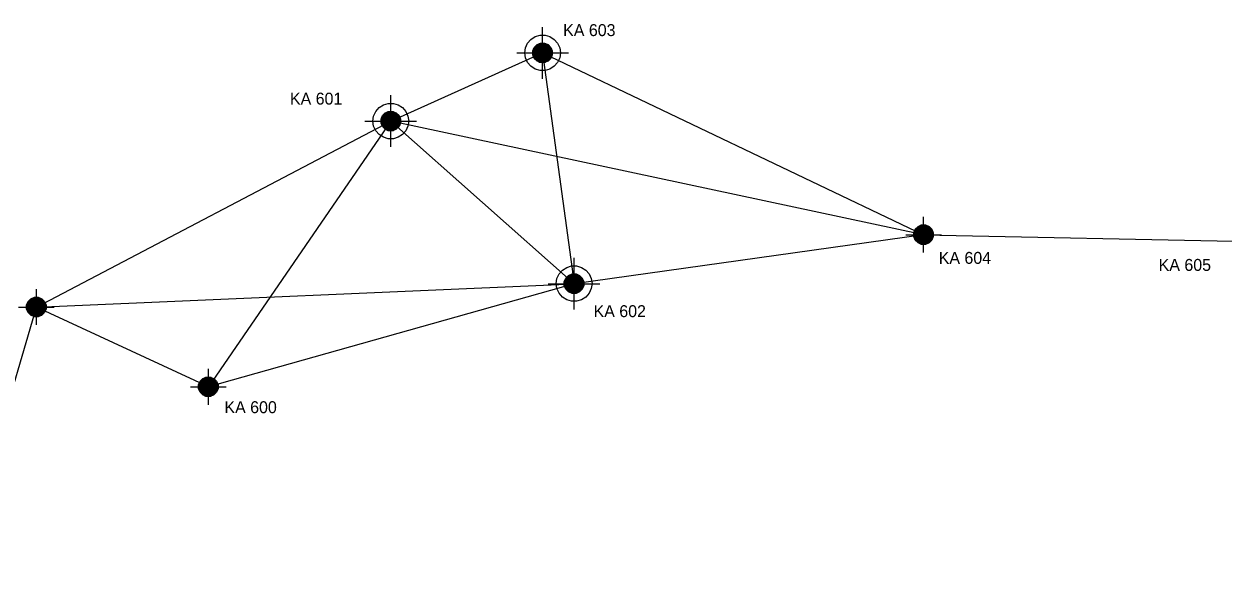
# Model space of a CAD drawing. Extents: x -346533 to -339969, y -1273090 to -1271585.
# Drawn here: x -342735 to -341982, y -1272262 to -1271911 of the extents above; entities that cross this region are included whole.
import ezdxf

# ---------------------------------------------------------------- set-up
doc = ezdxf.new("R2010")
doc.units = 0
for name, color, linetype in [('BP_11', 7, 'Continuous'), ('BP_12', 7, 'Continuous'), ('BP_14', 7, 'Continuous')]:
    doc.layers.add(name, color=color, linetype=linetype)

msp = doc.modelspace()

# ---------------------------------------------------------------- linework, layer by layer
at = {"layer": 'BP_11'}
for points in [[(-342409.41, -1271945.38), (-342409.41, -1271939.03), (-342409.41, -1271932.68), (-342409.41, -1271926.33), (-342409.41, -1271919.98), (-342409.41, -1271913.63), (-342409.41, -1271912.88)], [(-342425.66, -1271929.13), (-342419.31, -1271929.13), (-342412.96, -1271929.13), (-342406.61, -1271929.13), (-342400.26, -1271929.13), (-342393.91, -1271929.13), (-342393.16, -1271929.13)], [(-342409.41, -1271922.98), (-342408.21, -1271922.98), (-342405.96, -1271923.93), (-342404.26, -1271925.63), (-342403.31, -1271927.88), (-342403.31, -1271930.33), (-342404.26, -1271932.58), (-342405.96, -1271934.28), (-342408.21, -1271935.23), (-342410.66, -1271935.23), (-342412.91, -1271934.28), (-342414.61, -1271932.58), (-342415.56, -1271930.33), (-342415.56, -1271927.88), (-342414.61, -1271925.63), (-342412.91, -1271923.93), (-342410.66, -1271922.98), (-342409.46, -1271922.98), (-342407.66, -1271923.33), (-342411.26, -1271923.33), (-342412.06, -1271923.73), (-342406.86, -1271923.73), (-342406.06, -1271924.13), (-342412.41, -1271924.13), (-342412.86, -1271924.13), (-342413.26, -1271924.53), (-342406.91, -1271924.53), (-342405.66, -1271924.53), (-342405.26, -1271924.93), (-342411.61, -1271924.93), (-342413.66, -1271924.93), (-342414.06, -1271925.33), (-342407.71, -1271925.33), (-342404.86, -1271925.33), (-342404.46, -1271925.73), (-342410.81, -1271925.73), (-342414.46, -1271925.73), (-342414.46, -1271926.13), (-342408.11, -1271926.13), (-342404.46, -1271926.13), (-342404.06, -1271926.53), (-342410.41, -1271926.53), (-342414.86, -1271926.53), (-342414.86, -1271926.93), (-342408.51, -1271926.93), (-342404.06, -1271926.93), (-342404.06, -1271927.33), (-342410.41, -1271927.33), (-342414.86, -1271927.33), (-342415.26, -1271927.73), (-342408.91, -1271927.73), (-342403.66, -1271927.73), (-342403.66, -1271928.13), (-342410.01, -1271928.13), (-342415.26, -1271928.13), (-342415.26, -1271928.53), (-342408.91, -1271928.53), (-342403.66, -1271928.53), (-342403.66, -1271928.93), (-342410.01, -1271928.93), (-342415.26, -1271928.93), (-342415.26, -1271929.33), (-342408.91, -1271929.33), (-342403.66, -1271929.33), (-342403.66, -1271929.73), (-342410.01, -1271929.73), (-342415.26, -1271929.73), (-342415.26, -1271930.13), (-342408.91, -1271930.13), (-342403.66, -1271930.13), (-342403.66, -1271930.53), (-342410.01, -1271930.53), (-342415.26, -1271930.53), (-342415.26, -1271930.93), (-342408.91, -1271930.93), (-342403.66, -1271930.93), (-342404.06, -1271931.33), (-342410.41, -1271931.33), (-342414.86, -1271931.33), (-342414.86, -1271931.73), (-342408.51, -1271931.73), (-342404.06, -1271931.73), (-342404.46, -1271932.13), (-342410.81, -1271932.13), (-342414.46, -1271932.13), (-342414.46, -1271932.53), (-342408.11, -1271932.53), (-342404.46, -1271932.53), (-342404.86, -1271932.93), (-342411.21, -1271932.93), (-342414.06, -1271932.93), (-342413.66, -1271933.33), (-342407.31, -1271933.33), (-342405.26, -1271933.33), (-342405.66, -1271933.73), (-342412.01, -1271933.73), (-342413.26, -1271933.73), (-342412.86, -1271934.13), (-342406.51, -1271934.13), (-342406.06, -1271934.13)], [(-342406.06, -1271934.13), (-342406.86, -1271934.53), (-342412.06, -1271934.53), (-342411.26, -1271934.93), (-342407.66, -1271934.93)], [(-342504.81, -1271988.24), (-342504.81, -1271981.89), (-342504.81, -1271975.54), (-342504.81, -1271969.19), (-342504.81, -1271962.84), (-342504.81, -1271956.49), (-342504.81, -1271955.74)], [(-342504.81, -1271965.84), (-342503.61, -1271965.84), (-342501.36, -1271966.79), (-342499.66, -1271968.49), (-342498.71, -1271970.74), (-342498.71, -1271973.19), (-342499.66, -1271975.44), (-342501.36, -1271977.14), (-342503.61, -1271978.09), (-342506.06, -1271978.09), (-342508.31, -1271977.14), (-342510.01, -1271975.44), (-342510.96, -1271973.19), (-342510.96, -1271970.74), (-342510.01, -1271968.49), (-342508.31, -1271966.79), (-342506.06, -1271965.84), (-342504.86, -1271965.84), (-342503.06, -1271966.19), (-342506.66, -1271966.19), (-342507.46, -1271966.59), (-342502.26, -1271966.59), (-342501.46, -1271966.99), (-342507.81, -1271966.99), (-342508.26, -1271966.99), (-342508.66, -1271967.39), (-342502.31, -1271967.39), (-342501.06, -1271967.39), (-342500.66, -1271967.79), (-342507.01, -1271967.79), (-342509.06, -1271967.79), (-342509.46, -1271968.19), (-342503.11, -1271968.19), (-342500.26, -1271968.19), (-342499.86, -1271968.59), (-342506.21, -1271968.59), (-342509.86, -1271968.59), (-342509.86, -1271968.99), (-342503.51, -1271968.99), (-342499.86, -1271968.99), (-342499.46, -1271969.39), (-342505.81, -1271969.39), (-342510.26, -1271969.39), (-342510.26, -1271969.79), (-342503.91, -1271969.79), (-342499.46, -1271969.79), (-342499.46, -1271970.19), (-342505.81, -1271970.19), (-342510.26, -1271970.19), (-342510.66, -1271970.59), (-342504.31, -1271970.59), (-342499.06, -1271970.59), (-342499.06, -1271970.99), (-342505.41, -1271970.99), (-342510.66, -1271970.99), (-342510.66, -1271971.39), (-342504.31, -1271971.39), (-342499.06, -1271971.39), (-342499.06, -1271971.79), (-342505.41, -1271971.79), (-342510.66, -1271971.79), (-342510.66, -1271972.19), (-342504.31, -1271972.19), (-342499.06, -1271972.19), (-342499.06, -1271972.59), (-342505.41, -1271972.59), (-342510.66, -1271972.59), (-342510.66, -1271972.99), (-342504.31, -1271972.99), (-342499.06, -1271972.99), (-342499.06, -1271973.39), (-342505.41, -1271973.39), (-342510.66, -1271973.39), (-342510.66, -1271973.79), (-342504.31, -1271973.79), (-342499.06, -1271973.79), (-342499.46, -1271974.19), (-342505.81, -1271974.19), (-342510.26, -1271974.19), (-342510.26, -1271974.59), (-342503.91, -1271974.59), (-342499.46, -1271974.59), (-342499.86, -1271974.99), (-342506.21, -1271974.99), (-342509.86, -1271974.99), (-342509.86, -1271975.39), (-342503.51, -1271975.39), (-342499.86, -1271975.39), (-342500.26, -1271975.79), (-342506.61, -1271975.79), (-342509.46, -1271975.79), (-342509.06, -1271976.19), (-342502.71, -1271976.19), (-342500.66, -1271976.19), (-342501.06, -1271976.59), (-342507.41, -1271976.59), (-342508.66, -1271976.59), (-342508.26, -1271976.99), (-342501.91, -1271976.99), (-342501.46, -1271976.99)], [(-342521.06, -1271971.99), (-342514.71, -1271971.99), (-342508.36, -1271971.99), (-342502.01, -1271971.99), (-342495.66, -1271971.99), (-342489.31, -1271971.99), (-342488.56, -1271971.99)], [(-342501.46, -1271976.99), (-342502.26, -1271977.39), (-342507.46, -1271977.39), (-342506.66, -1271977.79), (-342503.06, -1271977.79)], [(-342169.95, -1272054.61), (-342169.95, -1272048.26), (-342169.95, -1272041.91), (-342169.95, -1272035.56), (-342169.95, -1272032.11)], [(-342169.95, -1272037.21), (-342168.75, -1272037.21), (-342166.5, -1272038.16), (-342164.8, -1272039.86), (-342163.85, -1272042.11), (-342163.85, -1272044.56), (-342164.8, -1272046.81), (-342166.5, -1272048.51), (-342168.75, -1272049.46), (-342171.2, -1272049.46), (-342173.45, -1272048.51), (-342175.15, -1272046.81), (-342176.1, -1272044.56), (-342176.1, -1272042.11), (-342175.15, -1272039.86), (-342173.45, -1272038.16), (-342171.2, -1272037.21), (-342170, -1272037.21), (-342168.2, -1272037.56), (-342171.8, -1272037.56), (-342172.6, -1272037.96), (-342167.4, -1272037.96), (-342166.6, -1272038.36), (-342172.95, -1272038.36), (-342173.4, -1272038.36), (-342173.8, -1272038.76), (-342167.45, -1272038.76), (-342166.2, -1272038.76), (-342165.8, -1272039.16), (-342172.15, -1272039.16), (-342174.2, -1272039.16), (-342174.6, -1272039.56), (-342168.25, -1272039.56), (-342165.4, -1272039.56), (-342165, -1272039.96), (-342171.35, -1272039.96), (-342175, -1272039.96), (-342175, -1272040.36), (-342168.65, -1272040.36), (-342165, -1272040.36), (-342164.6, -1272040.76), (-342170.95, -1272040.76), (-342175.4, -1272040.76), (-342175.4, -1272041.16), (-342169.05, -1272041.16), (-342164.6, -1272041.16), (-342164.2, -1272041.56), (-342170.55, -1272041.56), (-342175.8, -1272041.56), (-342175.8, -1272041.96), (-342169.45, -1272041.96), (-342164.2, -1272041.96), (-342164.2, -1272042.36), (-342170.55, -1272042.36), (-342175.8, -1272042.36), (-342175.8, -1272042.76), (-342169.45, -1272042.76), (-342164.2, -1272042.76), (-342164.2, -1272043.16), (-342170.55, -1272043.16), (-342175.8, -1272043.16), (-342175.8, -1272043.56), (-342169.45, -1272043.56), (-342164.2, -1272043.56), (-342164.2, -1272043.96), (-342170.55, -1272043.96), (-342175.8, -1272043.96), (-342175.8, -1272044.36), (-342169.45, -1272044.36), (-342164.2, -1272044.36), (-342164.2, -1272044.76), (-342170.55, -1272044.76), (-342175.8, -1272044.76), (-342175.8, -1272045.16), (-342169.45, -1272045.16), (-342164.2, -1272045.16), (-342164.6, -1272045.56), (-342170.95, -1272045.56), (-342175.4, -1272045.56), (-342175.4, -1272045.96), (-342169.05, -1272045.96), (-342164.6, -1272045.96), (-342165, -1272046.36), (-342171.35, -1272046.36), (-342175, -1272046.36), (-342175, -1272046.76), (-342168.65, -1272046.76), (-342165, -1272046.76), (-342165.4, -1272047.16), (-342171.75, -1272047.16), (-342174.6, -1272047.16), (-342174.2, -1272047.56), (-342167.85, -1272047.56), (-342165.8, -1272047.56), (-342166.2, -1272047.96), (-342172.55, -1272047.96), (-342173.8, -1272047.96), (-342173.4, -1272048.36), (-342167.05, -1272048.36), (-342166.6, -1272048.36)], [(-342181.2, -1272043.36), (-342174.85, -1272043.36), (-342168.5, -1272043.36), (-342162.15, -1272043.36), (-342158.7, -1272043.36)], [(-342166.6, -1272048.36), (-342167.4, -1272048.76), (-342172.6, -1272048.76), (-342171.8, -1272049.16), (-342168.2, -1272049.16)], [(-342389.61, -1272090.4), (-342389.61, -1272084.05), (-342389.61, -1272077.7), (-342389.61, -1272071.35), (-342389.61, -1272065), (-342389.61, -1272058.65), (-342389.61, -1272057.9)], [(-342389.61, -1272068), (-342388.41, -1272068), (-342386.16, -1272068.95), (-342384.46, -1272070.65), (-342383.51, -1272072.9), (-342383.51, -1272075.35), (-342384.46, -1272077.6), (-342386.16, -1272079.3), (-342388.41, -1272080.25), (-342390.86, -1272080.25), (-342393.11, -1272079.3), (-342394.81, -1272077.6), (-342395.76, -1272075.35), (-342395.76, -1272072.9), (-342394.81, -1272070.65), (-342393.11, -1272068.95), (-342390.86, -1272068), (-342389.66, -1272068), (-342387.86, -1272068.35), (-342391.46, -1272068.35), (-342392.26, -1272068.75), (-342387.06, -1272068.75), (-342386.26, -1272069.15), (-342392.61, -1272069.15), (-342393.06, -1272069.15), (-342393.46, -1272069.55), (-342387.11, -1272069.55), (-342385.86, -1272069.55), (-342385.46, -1272069.95), (-342391.81, -1272069.95), (-342393.86, -1272069.95), (-342394.26, -1272070.35), (-342387.91, -1272070.35), (-342385.06, -1272070.35), (-342384.66, -1272070.75), (-342391.01, -1272070.75), (-342394.66, -1272070.75), (-342394.66, -1272071.15), (-342388.31, -1272071.15), (-342384.66, -1272071.15), (-342384.26, -1272071.55), (-342390.61, -1272071.55), (-342395.06, -1272071.55), (-342395.06, -1272071.95), (-342388.71, -1272071.95), (-342384.26, -1272071.95), (-342384.26, -1272072.35), (-342390.61, -1272072.35), (-342395.06, -1272072.35), (-342395.46, -1272072.75), (-342389.11, -1272072.75), (-342383.86, -1272072.75), (-342383.86, -1272073.15), (-342390.21, -1272073.15), (-342395.46, -1272073.15), (-342395.46, -1272073.55), (-342389.11, -1272073.55), (-342383.86, -1272073.55), (-342383.86, -1272073.95), (-342390.21, -1272073.95), (-342395.46, -1272073.95), (-342395.46, -1272074.35), (-342389.11, -1272074.35), (-342383.86, -1272074.35), (-342383.86, -1272074.75), (-342390.21, -1272074.75), (-342395.46, -1272074.75), (-342395.46, -1272075.15), (-342389.11, -1272075.15), (-342383.86, -1272075.15), (-342383.86, -1272075.55), (-342390.21, -1272075.55), (-342395.46, -1272075.55), (-342395.46, -1272075.95), (-342389.11, -1272075.95), (-342383.86, -1272075.95), (-342384.26, -1272076.35), (-342390.61, -1272076.35), (-342395.06, -1272076.35), (-342395.06, -1272076.75), (-342388.71, -1272076.75), (-342384.26, -1272076.75), (-342384.66, -1272077.15), (-342391.01, -1272077.15), (-342394.66, -1272077.15), (-342394.66, -1272077.55), (-342388.31, -1272077.55), (-342384.66, -1272077.55), (-342385.06, -1272077.95), (-342391.41, -1272077.95), (-342394.26, -1272077.95), (-342393.86, -1272078.35), (-342387.51, -1272078.35), (-342385.46, -1272078.35), (-342385.86, -1272078.75), (-342392.21, -1272078.75), (-342393.46, -1272078.75), (-342393.06, -1272079.15), (-342386.71, -1272079.15), (-342386.26, -1272079.15)], [(-342727.59, -1272100.1), (-342727.59, -1272093.75), (-342727.59, -1272087.4), (-342727.59, -1272081.05), (-342727.59, -1272077.6)], [(-342405.86, -1272074.15), (-342399.51, -1272074.15), (-342393.16, -1272074.15), (-342386.81, -1272074.15), (-342380.46, -1272074.15), (-342374.11, -1272074.15), (-342373.36, -1272074.15)], [(-342386.26, -1272079.15), (-342387.06, -1272079.55), (-342392.26, -1272079.55), (-342391.46, -1272079.95), (-342387.86, -1272079.95)], [(-342727.59, -1272082.7), (-342726.39, -1272082.7), (-342724.14, -1272083.65), (-342722.44, -1272085.35), (-342721.49, -1272087.6), (-342721.49, -1272090.05), (-342722.44, -1272092.3), (-342724.14, -1272094), (-342726.39, -1272094.95), (-342728.84, -1272094.95), (-342731.09, -1272094), (-342732.79, -1272092.3), (-342733.74, -1272090.05), (-342733.74, -1272087.6), (-342732.79, -1272085.35), (-342731.09, -1272083.65), (-342728.84, -1272082.7), (-342727.64, -1272082.7), (-342725.84, -1272083.05), (-342729.44, -1272083.05), (-342730.24, -1272083.45), (-342725.04, -1272083.45), (-342724.24, -1272083.85), (-342730.59, -1272083.85), (-342731.04, -1272083.85), (-342731.44, -1272084.25), (-342725.09, -1272084.25), (-342723.84, -1272084.25), (-342723.44, -1272084.65), (-342729.79, -1272084.65), (-342731.84, -1272084.65), (-342732.24, -1272085.05), (-342725.89, -1272085.05), (-342723.04, -1272085.05), (-342722.64, -1272085.45), (-342728.99, -1272085.45), (-342732.64, -1272085.45), (-342732.64, -1272085.85), (-342726.29, -1272085.85), (-342722.64, -1272085.85), (-342722.24, -1272086.25), (-342728.59, -1272086.25), (-342733.04, -1272086.25), (-342733.04, -1272086.65), (-342726.69, -1272086.65), (-342722.24, -1272086.65), (-342721.84, -1272087.05), (-342728.19, -1272087.05), (-342733.44, -1272087.05), (-342733.44, -1272087.45), (-342727.09, -1272087.45), (-342721.84, -1272087.45), (-342721.84, -1272087.85), (-342728.19, -1272087.85), (-342733.44, -1272087.85), (-342733.44, -1272088.25), (-342727.09, -1272088.25), (-342721.84, -1272088.25), (-342721.84, -1272088.65), (-342728.19, -1272088.65), (-342733.44, -1272088.65), (-342733.44, -1272089.05), (-342727.09, -1272089.05), (-342721.84, -1272089.05), (-342721.84, -1272089.45), (-342728.19, -1272089.45), (-342733.44, -1272089.45), (-342733.44, -1272089.85), (-342727.09, -1272089.85), (-342721.84, -1272089.85), (-342721.84, -1272090.25), (-342728.19, -1272090.25), (-342733.44, -1272090.25), (-342733.44, -1272090.65), (-342727.09, -1272090.65), (-342721.84, -1272090.65), (-342722.24, -1272091.05), (-342728.59, -1272091.05), (-342733.04, -1272091.05), (-342733.04, -1272091.45), (-342726.69, -1272091.45), (-342722.24, -1272091.45), (-342722.64, -1272091.85), (-342728.99, -1272091.85), (-342732.64, -1272091.85), (-342732.64, -1272092.25), (-342726.29, -1272092.25), (-342722.64, -1272092.25), (-342723.04, -1272092.65), (-342729.39, -1272092.65), (-342732.24, -1272092.65), (-342731.84, -1272093.05), (-342725.49, -1272093.05), (-342723.44, -1272093.05), (-342723.84, -1272093.45), (-342730.19, -1272093.45), (-342731.44, -1272093.45), (-342731.04, -1272093.85), (-342724.69, -1272093.85), (-342724.24, -1272093.85)], [(-342738.84, -1272088.85), (-342732.49, -1272088.85), (-342726.14, -1272088.85), (-342719.79, -1272088.85), (-342716.34, -1272088.85)], [(-342724.24, -1272093.85), (-342725.04, -1272094.25), (-342730.24, -1272094.25), (-342729.44, -1272094.65), (-342725.84, -1272094.65)], [(-342619.47, -1272150.22), (-342619.47, -1272143.87), (-342619.47, -1272137.52), (-342619.47, -1272131.17), (-342619.47, -1272127.72)], [(-342630.72, -1272138.97), (-342624.37, -1272138.97), (-342618.02, -1272138.97), (-342611.67, -1272138.97), (-342608.22, -1272138.97)], [(-342619.47, -1272132.82), (-342618.27, -1272132.82), (-342616.02, -1272133.77), (-342614.32, -1272135.47), (-342613.37, -1272137.72), (-342613.37, -1272140.17), (-342614.32, -1272142.42), (-342616.02, -1272144.12), (-342618.27, -1272145.07), (-342620.72, -1272145.07), (-342622.97, -1272144.12), (-342624.67, -1272142.42), (-342625.62, -1272140.17), (-342625.62, -1272137.72), (-342624.67, -1272135.47), (-342622.97, -1272133.77), (-342620.72, -1272132.82), (-342619.52, -1272132.82), (-342617.72, -1272133.17), (-342621.32, -1272133.17), (-342622.12, -1272133.57), (-342616.92, -1272133.57), (-342616.12, -1272133.97), (-342622.47, -1272133.97), (-342622.92, -1272133.97), (-342623.32, -1272134.37), (-342616.97, -1272134.37), (-342615.72, -1272134.37), (-342615.32, -1272134.77), (-342621.67, -1272134.77), (-342623.72, -1272134.77), (-342624.12, -1272135.17), (-342617.77, -1272135.17), (-342614.92, -1272135.17), (-342614.52, -1272135.57), (-342620.87, -1272135.57), (-342624.52, -1272135.57), (-342624.52, -1272135.97), (-342618.17, -1272135.97), (-342614.52, -1272135.97), (-342614.12, -1272136.37), (-342620.47, -1272136.37), (-342624.92, -1272136.37), (-342624.92, -1272136.77), (-342618.57, -1272136.77), (-342614.12, -1272136.77), (-342613.72, -1272137.17), (-342620.07, -1272137.17), (-342625.32, -1272137.17), (-342625.32, -1272137.57), (-342618.97, -1272137.57), (-342613.72, -1272137.57), (-342613.72, -1272137.97), (-342620.07, -1272137.97), (-342625.32, -1272137.97), (-342625.32, -1272138.37), (-342618.97, -1272138.37), (-342613.72, -1272138.37), (-342613.72, -1272138.77), (-342620.07, -1272138.77), (-342625.32, -1272138.77), (-342625.32, -1272139.17), (-342618.97, -1272139.17), (-342613.72, -1272139.17), (-342613.72, -1272139.57), (-342620.07, -1272139.57), (-342625.32, -1272139.57), (-342625.32, -1272139.97), (-342618.97, -1272139.97), (-342613.72, -1272139.97), (-342613.72, -1272140.37), (-342620.07, -1272140.37), (-342625.32, -1272140.37), (-342625.32, -1272140.77), (-342618.97, -1272140.77), (-342613.72, -1272140.77), (-342614.12, -1272141.17), (-342620.47, -1272141.17), (-342624.92, -1272141.17), (-342624.92, -1272141.57), (-342618.57, -1272141.57), (-342614.12, -1272141.57), (-342614.52, -1272141.97), (-342620.87, -1272141.97), (-342624.52, -1272141.97), (-342624.52, -1272142.37), (-342618.17, -1272142.37), (-342614.52, -1272142.37), (-342614.92, -1272142.77), (-342621.27, -1272142.77), (-342624.12, -1272142.77), (-342623.72, -1272143.17), (-342617.37, -1272143.17), (-342615.32, -1272143.17), (-342615.72, -1272143.57), (-342622.07, -1272143.57), (-342623.32, -1272143.57), (-342622.92, -1272143.97), (-342616.57, -1272143.97), (-342616.12, -1272143.97)], [(-342616.12, -1272143.97), (-342616.92, -1272144.37), (-342622.12, -1272144.37), (-342621.32, -1272144.77), (-342617.72, -1272144.77)]]:
    msp.add_lwpolyline(points, dxfattribs=at)
for points in [[(-342407.81, -1271917.98), (-342404.76, -1271918.88), (-342402.06, -1271920.63), (-342399.96, -1271923.03), (-342398.61, -1271925.93), (-342398.16, -1271929.08), (-342398.61, -1271932.23), (-342399.96, -1271935.13), (-342402.06, -1271937.53), (-342404.76, -1271939.28), (-342407.81, -1271940.18), (-342411.01, -1271940.18), (-342414.06, -1271939.28), (-342416.76, -1271937.53), (-342418.86, -1271935.13), (-342420.21, -1271932.23), (-342420.66, -1271929.08), (-342420.21, -1271925.93), (-342418.86, -1271923.03), (-342416.76, -1271920.63), (-342414.06, -1271918.88), (-342411.01, -1271917.98)], [(-342503.21, -1271960.84), (-342500.16, -1271961.74), (-342497.46, -1271963.49), (-342495.36, -1271965.89), (-342494.01, -1271968.79), (-342493.56, -1271971.94), (-342494.01, -1271975.09), (-342495.36, -1271977.99), (-342497.46, -1271980.39), (-342500.16, -1271982.14), (-342503.21, -1271983.04), (-342506.41, -1271983.04), (-342509.46, -1271982.14), (-342512.16, -1271980.39), (-342514.26, -1271977.99), (-342515.61, -1271975.09), (-342516.06, -1271971.94), (-342515.61, -1271968.79), (-342514.26, -1271965.89), (-342512.16, -1271963.49), (-342509.46, -1271961.74), (-342506.41, -1271960.84)], [(-342168.75, -1272037.21), (-342166.5, -1272038.16), (-342164.8, -1272039.86), (-342163.85, -1272042.11), (-342163.85, -1272044.56), (-342164.8, -1272046.81), (-342166.5, -1272048.51), (-342168.75, -1272049.46), (-342171.2, -1272049.46), (-342173.45, -1272048.51), (-342175.15, -1272046.81), (-342176.1, -1272044.56), (-342176.1, -1272042.11), (-342175.15, -1272039.86), (-342173.45, -1272038.16), (-342171.2, -1272037.21)], [(-342388.01, -1272063), (-342384.96, -1272063.9), (-342382.26, -1272065.65), (-342380.16, -1272068.05), (-342378.81, -1272070.95), (-342378.36, -1272074.1), (-342378.81, -1272077.25), (-342380.16, -1272080.15), (-342382.26, -1272082.55), (-342384.96, -1272084.3), (-342388.01, -1272085.2), (-342391.21, -1272085.2), (-342394.26, -1272084.3), (-342396.96, -1272082.55), (-342399.06, -1272080.15), (-342400.41, -1272077.25), (-342400.86, -1272074.1), (-342400.41, -1272070.95), (-342399.06, -1272068.05), (-342396.96, -1272065.65), (-342394.26, -1272063.9), (-342391.21, -1272063)], [(-342726.39, -1272082.7), (-342724.14, -1272083.65), (-342722.44, -1272085.35), (-342721.49, -1272087.6), (-342721.49, -1272090.05), (-342722.44, -1272092.3), (-342724.14, -1272094), (-342726.39, -1272094.95), (-342728.84, -1272094.95), (-342731.09, -1272094), (-342732.79, -1272092.3), (-342733.74, -1272090.05), (-342733.74, -1272087.6), (-342732.79, -1272085.35), (-342731.09, -1272083.65), (-342728.84, -1272082.7)], [(-342618.27, -1272132.82), (-342616.02, -1272133.77), (-342614.32, -1272135.47), (-342613.37, -1272137.72), (-342613.37, -1272140.17), (-342614.32, -1272142.42), (-342616.02, -1272144.12), (-342618.27, -1272145.07), (-342620.72, -1272145.07), (-342622.97, -1272144.12), (-342624.67, -1272142.42), (-342625.62, -1272140.17), (-342625.62, -1272137.72), (-342624.67, -1272135.47), (-342622.97, -1272133.77), (-342620.72, -1272132.82)]]:
    msp.add_lwpolyline(points, close=True, dxfattribs=at)
at = {"layer": 'BP_14'}
for p, q in [((-342504.81, -1271971.99), (-342409.41, -1271929.13)), ((-342409.41, -1271929.13), (-342169.95, -1272043.36)), ((-342409.41, -1271929.13), (-342389.61, -1272074.15)), ((-342727.59, -1272088.85), (-342504.81, -1271971.99)), ((-342504.81, -1271971.99), (-342619.47, -1272138.97)), ((-342169.95, -1272043.36), (-342504.81, -1271971.99)), ((-342389.61, -1272074.15), (-342504.81, -1271971.99)), ((-342169.95, -1272043.36), (-342389.61, -1272074.15)), ((-342169.95, -1272043.36), (-341962.56, -1272047.71)), ((-342727.59, -1272088.85), (-342389.61, -1272074.15)), ((-342389.61, -1272074.15), (-342619.47, -1272138.97)), ((-342778.11, -1272261.67), (-342727.59, -1272088.85)), ((-342619.47, -1272138.97), (-342727.59, -1272088.85))]:
    msp.add_line(p, q, dxfattribs=at)

# ---------------------------------------------------------------- texts
at = {"layer": 'BP_12'}
for s, p in [('KA 603', (-342396.49, -1271918.54)), ('KA 601', (-342568.19, -1271961.6)), ('KA 604', (-342160.45, -1272061.7)), ('KA 605', (-342022.21, -1272066.11)), ('KA 602', (-342377.37, -1272095.18)), ('KA 600', (-342609.36, -1272155.54))]:
    msp.add_text(s, height=7.5, dxfattribs=at).set_placement(p)

doc.saveas('drawing.dxf')
